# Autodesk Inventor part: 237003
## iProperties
Created: 2006-08
Part Number: 237003
Material: FSt vz
Description: Federring
Vendor: Autodesk Inc.
Document SubType Name: Modeling
Standard: DIN 127
Designer: I.Baliuc
Standards Organization: DIN
Language: de-DE
Size Designation: A 8
Categories: <MemberInstance Version="R10.0.0"><Categories><Category DisplayName="Schrauben" InternalName="e4da775c-781d-43d5-af7c-5136215cf5a6" Mnemonic="FSTN"><Category Di
Density: 7.85 g/cm^3
Mass: 1.77015 g
Surface Area: 3.83339 cm^2
Volume: 0.225497 cm^3
Abmessung: A 8
Author: T.Messerschmitt
Comments: DIN 127 - A 8
Revision Number: 237003
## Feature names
1. Körper [Extrusion]
2. Schnitt [Extrusion]
